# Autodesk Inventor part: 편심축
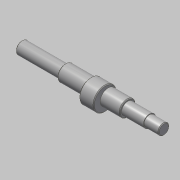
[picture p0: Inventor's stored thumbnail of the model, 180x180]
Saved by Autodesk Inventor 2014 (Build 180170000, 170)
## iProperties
Created: 2016-05
Part Number: 편심축
Document SubType Name: Modeling
Designer: mduedu
Density: 7.86 g/cm^3
Material: 강철, 연강
Appearance: Steel
Author: mduedu
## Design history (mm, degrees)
sketch "스케치1"
  geometry: L1 (-38, 11)-(-38, 8.5); L2 (48, 11)-(48, 8.5); L3 (-98, 0)-(98, 0); L4 (-38, 11)-(48, 11); L5 (48, 11)-(48, 8.5); L6 (-38, 11)-(-38, 8.5); L7 (-38, 8.5)-(-98, 8.5); L8 (-98, 8.5)-(-98, 0); L9 (48, 8.5)-(78, 8.5); L10 (98, 7.5)-(98, 0); L11 (78, 8.5)-(78, 7.5); L12 (78, 7.5)-(98, 7.5); 1 further point
  constraints: 24 end point, 9 perpendicular, 2 midpoint, 1 collinear, 1 horizontal
  dimensions: "d0" = 22 diameter of L4 L3; "d1" = 17 diameter of L7 L3; "d2" = 60 distance between parallel lines of L8 L1; "d3" = 50 distance between parallel lines of L10 L2; "d4" = 15 diameter of L12 L3; "d5" = 20 distance between parallel lines of L10 L11; "d29" = 86 distance of L1.start L2.start
revolve "회전1" stored, may be unused: angle "d6" = 90 deg
node "작업 평면7"
node "작업 평면9"
sketch "스케치2"
  geometry: C1 r 11 at (0, 0); C2 r 16 at (0, -4); C3 r 11 at (0, 0); 2 further points
  constraints: 3 centre point, 2 coincident, 1 concentric, 1 vertical alignment
  dimensions: "d9" = 4 distance of point (0, 0) C2.centre; "d10" = 32 diameter of C2
extrude "돌출1" join sketch "스케치2" stored distance "d11" = 20; taper "d12" = 0 deg
chamfer "모따기1" distance "d17" = 1; stored, may be unused: second distance "d18" = 2, angle "d19" = 45 deg
node "작업 평면4"
sketch "스케치4"
  geometry: L1 (-10, -6.5)-(-10, 6.5) reference; L2 (-5, 2.5)-(5, 2.5); L3 (5, -2.5)-(-5, -2.5); A1 r 2.5 centre (5, 0) between (5, -2.5) and (5, 2.5); A2 r 2.5 centre (-5, 0) between (-5, 2.5) and (-5, -2.5); 2 further points
  constraints: 4 end point, 4 point on circle, 4 tangent, 2 centre point, 1 horizontal alignment, 1 midpoint, 1 parallel, 1 perpendicular
  dimensions: "d20" = 5 distance between parallel lines of L3 L2; "d21" = 15 dimension on A1 A2; "d22" = 2.5 distance edge to line of A2 L1
extrude "돌출3" cut sketch "스케치4" distance "d23" = 3; taper "d24" = 0 deg
node "작업 평면5"
sketch "스케치5"
  geometry: L1 (30, 7.5)-(30, -7.5) reference; L2 (30, 2.5)-(12.5, 2.5); L3 (12.5, -2.5)-(30, -2.5); A1 r 2.5 centre (12.5, 0) between (12.5, 2.5) and (12.5, -2.5); 2 further points
  constraints: 4 end point, 2 perpendicular, 2 point on circle, 2 point on line, 2 tangent, 1 centre point, 1 horizontal alignment, 1 midpoint
  dimensions: "d25" = 5 distance between parallel lines of L3 L2; "d26" = 20 dimension on A1 L1
extrude "돌출4" cut sketch "스케치5" distance "d27" = 3; taper "d28" = 0 deg
node "솔리드1"
other parameters: "d31" = -37
